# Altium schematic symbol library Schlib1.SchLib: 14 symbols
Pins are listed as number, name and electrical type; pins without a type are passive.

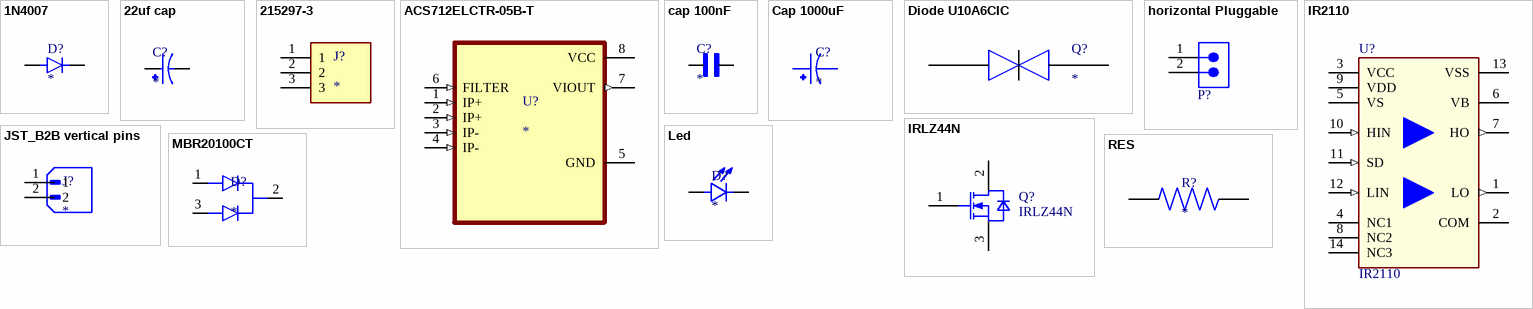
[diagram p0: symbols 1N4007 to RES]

## 1N4007
designator D?
Diode, DO-41, 1000V, 1A, 175Â°C; MF: Diotec Semiconductor; MP: 1N4007
footprint 1N4007
pins: A, C

## 22uf cap
designator C?
CAP ALUM 22UF 20% 400V RADIAL; MF: Panasonic; MP: EEU-ED2G220S
footprint cap 22uf 50V (Aluminum Electrolytic Capacitors, 8x11.5mm)
pins: N, P

## 215297-3
designator J?
3 Position Receptacle Black 2.54 mm Pitch Through Hole Vertical Header; MP: 215297-3; Product_Type: Connector; MF: TE Connectivity; Centerline_Pitch: 2.54 mm[.1 in]; Number_of_Positions: 3
footprint TE_215297-3
pins: 1, 2, 3

## ACS712ELCTR-05B-T
designator U?
MF: {'manufacturer': u'Allegro MicroSystems'}; MP: ACS712ELCTR-05B-T
footprint SOIC127P600X175-8N
pins: 1 IP+ (in), 2 IP+ (in), 3 IP- (in), 4 IP- (in), 5 GND (power), 6 FILTER (in), 7 VIOUT (out), 8 VCC (power)

## cap 100nF
designator C?
Capacitor, Ceramic, 100nF, 100VDC, 10-% Tol, 10+% Tol, X7R-TC Code, -15, 15%-TC; MF: AVX; MP: SR291C104KARTR1
footprint CAP ceramic
pins: 1, 2

## Cap 1000uF
designator C?
12.5*20mm            330 ÂµF 50 V Aluminum Electrolytic Capacitors Radial, Can - 10000 Hrs @ 125Â°C; MP: UBT1H331MHD8; MF: Nichicon
footprint Cap 1000uF
pins: N NEG, P POS

## Diode U10A6CIC
designator Q?
Ultra Fast Recovery Rectifier Diode 600V 10A; MF: Vishay Siliconix; MP: IRF9640
footprint TO254P1066X482X2286-3
pins: 1 Anode, 2 Cathode, 3 Anode

## horizontal Pluggable
designator P?, comment 691305540002  (value not drawn)
WR-TBL Series 3055 PCB Header Horizontal Entry with Plastic Latches, THT, pitch 5.08mm, 2p; Manufacturer: Wurth Elektronik; Modularity: No; Rated Current: 16A; Working Voltage: 300V
footprint Horizontal Pluggable (5,08mm - PCB Header Horizontal Entry with Plastic Latches - 02p)
pins: 1, 2

## IR2110
designator U?
High and Low Side Driver; Manufacturer: Infineon Technologies
footprint DIP762W46P254L1930H533Q14B (DIP,7.62mm lead span,2.54mm pitch;14 pin,6.605mm W X 19.305mm L X 5.33mm H body)
pins: 1 LO (out) "Low side gate drive output", 2 COM (power) "Low side return", 3 VCC (power) "Low side supply", 4 NC1, 5 VS (power) "High side floating supply return", 6 VB (power) "High side floating supply", 7 HO (out) "High side gate drive output", 8 NC2, 9 VDD (power) "Logic Supply", 10 HIN (in) "Logic input for high side gate driver outputs (HO), in phase", 11 SD (in) "Logic input for shutdown", 12 LIN (in) "Logic input for low side gate driver outputs (LO), in phase", 13 VSS (power) "Logic ground", 14 NC3

## IRLZ44N
designator Q?
OptiMOS 3 Power-Transistor, VDS 100V; Manufacturer: Infineon Technologies
footprint IFX-PG-TO220-3-904-1 (TO,flange mount,2.54 mm pitch, 3 pin, 10.16 mm L X 4.57 mm W X 20.56 mm H body)
pins: 1 GATE, 2 DRAIN, 3 SOURCE

## JST_B2B vertical pins
designator J?
Connector Header Through Hole 2 position 0.098 (2.50mm); MF: JST Sales; MP: B2B-XH-A (LF)(SN)
footprint JST_B2B vertical pins
pins: 1, 2

## Led
designator D?
LED 597-6901-607F, 597 Series White LED, 3216 (1206), Round Lens SMD package ¦ Dialight 597-6901-607F
footprint LED
footprint LED (LED_WP7113SEC/J3)
pins: A, C

## MBR20100CT
designator D?
Diode Array 1 Pair Common Cathode Schottky 100 V 10A Through Hole TO-262-3 Long Leads, IÂ²Pak, TO-262AA; MF: Diodes Inc.; MP: MBR20100CT
footprint TO254P1066X482X2286-3
pins: 1 ANODE1, 2 COMMON_CATHODE, 3 ANODE2

## RES
designator R?
1.07 kOhms Â±1% 0.25W, 1/4W Through Hole Resistor Axial - Metal Film; MF: Yageo; MP: MFR-25FBF52-1K
footprint RES
pins: 1, 2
